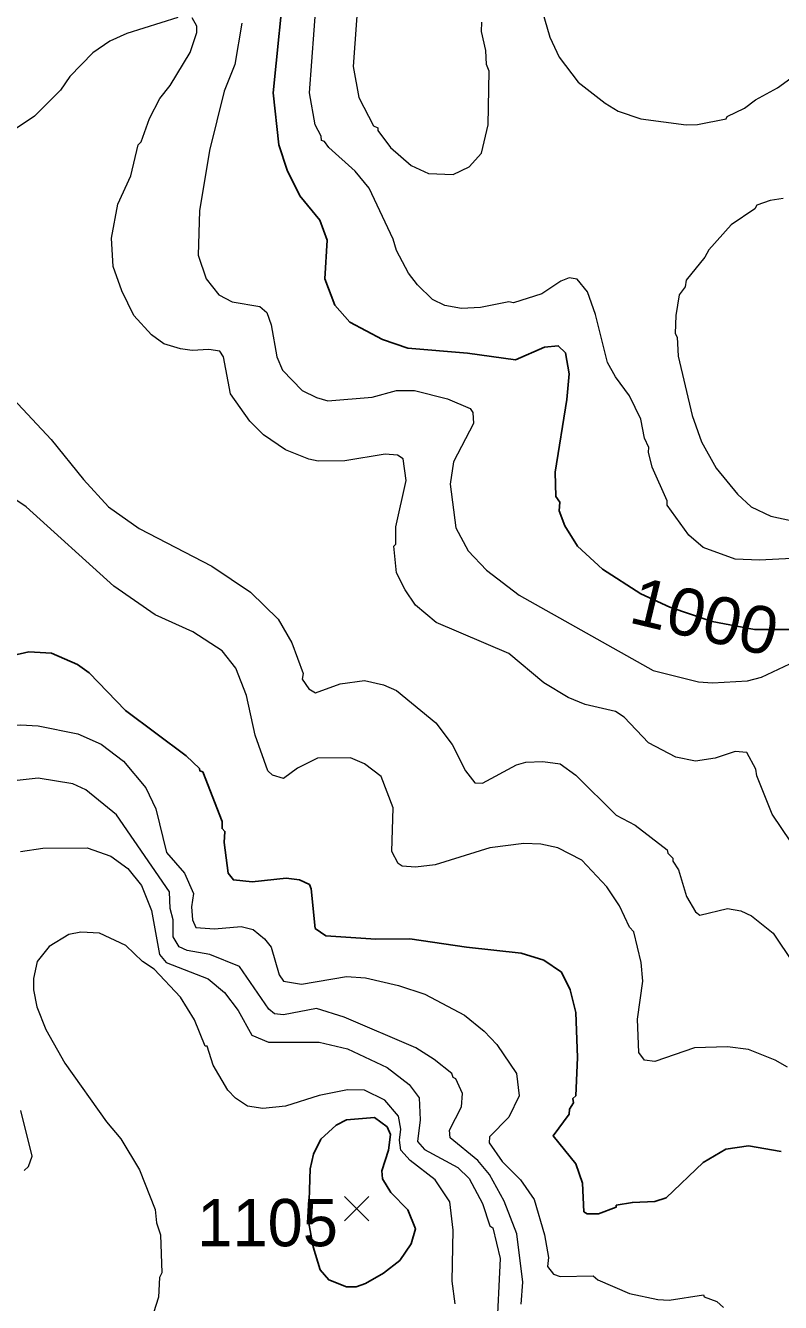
# Model space of a CAD drawing. Extents: x 265.7 to 292.1, y 7676.2 to 7704.2.
# Drawn here: x 289.907 to 291.184, y 7678.572 to 7680.733 of the extents above; entities that cross this region are included whole.
import ezdxf
from ezdxf.enums import TextEntityAlignment as Align

# ---------------------------------------------------------------- set-up
doc = ezdxf.new("R2010")
doc.units = 0
doc.header["$LTSCALE"] = 0.032
for name, color, linetype, lineweight in [('1', 7, 'Continuous', 25), ('2', 7, 'Continuous', 13), ('21', 7, 'Continuous', 25)]:
    doc.layers.add(name, color=color, linetype=linetype, lineweight=lineweight)
doc.layers.add('61', color=7, linetype='Continuous')

msp = doc.modelspace()

# ---------------------------------------------------------------- linework, layer by layer
at = {"layer": '1'}
for points in [[(290.3464, 7680.8268), (290.3256, 7680.6193), (290.3352, 7680.5316), (290.3495, 7680.4885), (290.3711, 7680.4454), (290.4046, 7680.4039), (290.4174, 7680.3704), (290.4134, 7680.3049), (290.4301, 7680.2602), (290.4557, 7680.2315), (290.5107, 7680.202), (290.5538, 7680.1876), (290.6544, 7680.1789), (290.7358, 7680.1677)], [(290.7358, 7680.1677), (290.7852, 7680.1892), (290.8084, 7680.1916), (290.8203, 7680.1797), (290.8267, 7680.1438), (290.8227, 7680.1007), (290.8028, 7679.9778)], [(290.8028, 7679.9778), (290.8044, 7679.9363), (290.8108, 7679.9267), (290.81, 7679.9123), (290.8195, 7679.8868), (290.8411, 7679.8525), (290.8834, 7679.8134), (290.948, 7679.7719), (290.997, 7679.7492), (291.0687, 7679.7247), (291.1403, 7679.7115), (291.2176, 7679.7115)], [(291.1858, 7678.8279), (291.13, 7678.8375), (291.0917, 7678.8319), (291.0534, 7678.8095), (290.9911, 7678.7497), (290.972, 7678.7433), (290.9337, 7678.7417), (290.9065, 7678.7369), (290.9065, 7678.7337), (290.8762, 7678.7226), (290.8571, 7678.7226), (290.8515, 7678.7258), (290.8491, 7678.7745), (290.8379, 7678.8072), (290.7996, 7678.8542), (290.8267, 7678.891), (290.8275, 7678.8997), (290.8339, 7678.9101), (290.8331, 7678.9173), (290.8379, 7678.9221), (290.8411, 7678.9867), (290.8379, 7679.0633), (290.8283, 7679.1016), (290.814, 7679.1311), (290.7836, 7679.1519), (290.7453, 7679.1638), (290.6528, 7679.1734), (290.557, 7679.1878), (290.4996, 7679.187), (290.415, 7679.1926), (290.3966, 7679.2053), (290.3902, 7679.2724), (290.387, 7679.2796), (290.3703, 7679.2875), (290.348, 7679.2907), (290.2905, 7679.2843), (290.2586, 7679.2875), (290.2498, 7679.2987), (290.2426, 7679.3506), (290.2442, 7679.3697), (290.2394, 7679.3745), (290.2394, 7679.3865), (290.2067, 7679.4703), (290.2019, 7679.4719), (290.2011, 7679.4759), (290.1788, 7679.4974), (290.0759, 7679.574), (290.0144, 7679.6378), (289.9945, 7679.6522), (289.9506, 7679.6713), (289.9123, 7679.6737), (289.8851, 7679.6674)]]:
    msp.add_lwpolyline(points, dxfattribs=at)
msp.add_lwpolyline([(290.3856, 7678.7093), (290.3933, 7678.6663), (290.4054, 7678.6276), (290.4198, 7678.6109), (290.4501, 7678.5989), (290.4661, 7678.5989), (290.482, 7678.6045), (290.5123, 7678.622), (290.5403, 7678.6436), (290.5594, 7678.6715), (290.5666, 7678.697), (290.5538, 7678.729), (290.5251, 7678.7585), (290.5107, 7678.7816), (290.5099, 7678.7952), (290.5211, 7678.8303), (290.5243, 7678.8566), (290.5187, 7678.8694), (290.4972, 7678.8854), (290.4501, 7678.8814), (290.4325, 7678.8726), (290.4062, 7678.8486), (290.3942, 7678.8231), (290.3886, 7678.7984)], close=True, dxfattribs=at)
at = {"layer": '2'}
for points in [[(290.4724, 7680.8204), (290.4613, 7680.664), (290.4708, 7680.6114), (290.4956, 7680.5635), (290.5028, 7680.5603), (290.5028, 7680.5555), (290.5243, 7680.5268), (290.5594, 7680.4964), (290.5889, 7680.4829), (290.6304, 7680.4813), (290.6576, 7680.4941), (290.6783, 7680.5172), (290.6895, 7680.5651), (290.6911, 7680.656), (290.6871, 7680.6672), (290.6855, 7680.6912), (290.6783, 7680.7231), (290.6791, 7680.739)], [(291.2257, 7679.8325), (291.1491, 7679.8286), (291.1076, 7679.8301), (291.0534, 7679.8501), (291.0294, 7679.8708), (290.9927, 7679.9219), (290.9927, 7679.9291), (290.9672, 7679.9858), (290.9608, 7680.0113), (290.9616, 7680.0193), (290.9544, 7680.0352), (290.948, 7680.0671), (290.9289, 7680.107), (290.9049, 7680.139), (290.8914, 7680.1629), (290.8714, 7680.2443), (290.8579, 7680.2826), (290.8403, 7680.3041), (290.8267, 7680.3065), (290.8124, 7680.3009), (290.7805, 7680.2794), (290.7326, 7680.2642), (290.7246, 7680.2658), (290.6767, 7680.2563), (290.6448, 7680.2547), (290.6161, 7680.2595), (290.5953, 7680.2698), (290.5698, 7680.2946), (290.5546, 7680.3145), (290.5347, 7680.3528), (290.5291, 7680.372), (290.4884, 7680.4581), (290.4645, 7680.4869), (290.4198, 7680.5268), (290.4126, 7680.5371), (290.4078, 7680.5387), (290.407, 7680.5459), (290.3966, 7680.5651), (290.3871, 7680.6193), (290.399, 7680.7789)], [(290.7812, 7680.7582), (290.794, 7680.7135), (290.81, 7680.68), (290.8419, 7680.6377), (290.8874, 7680.6018), (290.9097, 7680.5882), (290.948, 7680.5754), (291.0246, 7680.5651), (291.0438, 7680.5659), (291.0925, 7680.5754), (291.0941, 7680.5794), (291.1236, 7680.5938), (291.1419, 7680.6074), (291.1794, 7680.6281), (291.2145, 7680.6536)], [(290.1644, 7680.747), (290.0782, 7680.7199), (290.0495, 7680.7071), (290.0208, 7680.6872), (289.9817, 7680.6473), (289.9657, 7680.6241), (289.9218, 7680.5802), (289.8596, 7680.5387), (289.8165, 7680.518), (289.7607, 7680.5092), (289.6825, 7680.526), (289.5947, 7680.526), (289.5899, 7680.5228), (289.4989, 7680.5172), (289.4606, 7680.522), (289.4231, 7680.5435), (289.3968, 7680.5691), (289.3776, 7680.6018), (289.3505, 7680.68), (289.3441, 7680.7191), (289.3393, 7680.7207), (289.3369, 7680.7263), (289.3266, 7680.7334)], [(290.9201, 7679.5628), (290.9049, 7679.5724), (290.8539, 7679.5844), (290.8251, 7679.5963), (290.7836, 7679.6211), (290.7246, 7679.6706), (290.6017, 7679.7232), (290.5666, 7679.7527), (290.549, 7679.7783), (290.5347, 7679.807), (290.5299, 7679.8525), (290.5331, 7679.8557), (290.5331, 7679.8852), (290.5506, 7679.9634), (290.5459, 7680.0001), (290.5363, 7680.0065), (290.5155, 7680.0081), (290.4469, 7679.9969), (290.4022, 7679.9961), (290.3862, 7679.9993), (290.3464, 7680.0153), (290.3096, 7680.0408), (290.2865, 7680.064), (290.2538, 7680.1102), (290.2418, 7680.1725), (290.2354, 7680.1821), (290.2171, 7680.1852), (290.1884, 7680.1836), (290.1692, 7680.186), (290.1405, 7680.1948), (290.1197, 7680.21), (290.0902, 7680.2427), (290.0695, 7680.2842), (290.0551, 7680.3257), (290.0519, 7680.3736), (290.0631, 7680.431), (290.0846, 7680.4789), (290.0974, 7680.5316), (290.1022, 7680.5363), (290.1165, 7680.5762), (290.1341, 7680.6098), (290.1517, 7680.6321), (290.1852, 7680.688), (290.1963, 7680.7215), (290.1963, 7680.7326), (290.1884, 7680.7462)], [(290.2729, 7680.7374), (290.261, 7680.6672), (290.2426, 7680.6225), (290.2179, 7680.522), (290.2011, 7680.4198), (290.1987, 7680.3448), (290.2123, 7680.3049), (290.2338, 7680.2778), (290.2562, 7680.2658), (290.3033, 7680.2579), (290.3152, 7680.2475), (290.3224, 7680.2267), (290.332, 7680.1725), (290.3416, 7680.1501), (290.3751, 7680.1158), (290.399, 7680.1039), (290.4182, 7680.0983), (290.4932, 7680.1046), (290.5347, 7680.1158), (290.565, 7680.1158), (290.6209, 7680.1015), (290.6592, 7680.0855), (290.6639, 7680.0783), (290.6647, 7680.06), (290.6312, 7679.9953), (290.6256, 7679.957), (290.6352, 7679.8836), (290.656, 7679.8445), (290.6871, 7679.8118), (290.7422, 7679.7695), (290.9688, 7679.6418), (291.0454, 7679.6227), (291.0693, 7679.6211), (291.1284, 7679.6243), (291.1523, 7679.6307)], [(291.189, 7680.4406), (291.1667, 7680.4374), (291.1443, 7680.4294), (291.1411, 7680.423), (291.1012, 7680.3959), (291.0629, 7680.3536), (291.0565, 7680.3416), (291.0246, 7680.3025), (291.023, 7680.2914), (291.0127, 7680.2778), (291.0071, 7680.2427), (291.0063, 7680.2124), (291.0095, 7680.206), (291.0111, 7680.1741), (291.035, 7680.0735), (291.051, 7680.0288), (291.0757, 7679.9842), (291.1116, 7679.9403), (291.1348, 7679.9187), (291.1683, 7679.9028), (291.2018, 7679.8956)], [(289.8859, 7680.1015), (289.9498, 7680.0328), (290.0048, 7679.965), (290.0471, 7679.9187), (290.099, 7679.882), (290.2219, 7679.8182), (290.2873, 7679.7743), (290.3344, 7679.7288), (290.3575, 7679.6889), (290.3767, 7679.637), (290.3751, 7679.6275), (290.3863, 7679.6107), (290.3974, 7679.6043), (290.4389, 7679.6195), (290.4804, 7679.6251), (290.5123, 7679.6179), (290.5347, 7679.6083), (290.6009, 7679.5533), (290.6288, 7679.5166), (290.6512, 7679.4719), (290.6671, 7679.4519), (290.6799, 7679.4511), (290.7374, 7679.4822), (290.7533, 7679.487), (290.7821, 7679.4878), (290.8116, 7679.4838), (290.8379, 7679.4647), (290.9065, 7679.3969), (290.9385, 7679.3801), (290.9927, 7679.3386), (290.9935, 7679.333), (291.0023, 7679.3242), (291.0023, 7679.3195), (291.0119, 7679.3043), (291.0254, 7679.2596), (291.0406, 7679.2333), (291.0478, 7679.2277), (291.0949, 7679.2389), (291.1172, 7679.2349), (291.1355, 7679.2269), (291.1723, 7679.1974), (291.2066, 7679.1463)], [(291.1962, 7678.9707), (291.1754, 7678.9827), (291.13, 7679.0003), (291.0949, 7679.0051), (291.039, 7679.0035), (290.972, 7678.9803), (290.9544, 7678.9827), (290.9448, 7678.9955), (290.9424, 7679.0521), (290.9512, 7679.116), (290.9488, 7679.1479), (290.9361, 7679.1998), (290.9289, 7679.2077), (290.9121, 7679.2437), (290.8906, 7679.2756), (290.8483, 7679.321), (290.8076, 7679.3418), (290.7789, 7679.3482), (290.7501, 7679.349), (290.6927, 7679.3418), (290.6001, 7679.3131), (290.5666, 7679.3091), (290.5443, 7679.3107), (290.5371, 7679.3155), (290.5267, 7679.3354), (290.5291, 7679.4096), (290.5083, 7679.4623), (290.4804, 7679.4838), (290.4565, 7679.4942), (290.4006, 7679.4934), (290.3671, 7679.4766), (290.3432, 7679.4591), (290.3248, 7679.4647), (290.3168, 7679.4719), (290.2953, 7679.5325), (290.2809, 7679.5995), (290.2626, 7679.6458), (290.2394, 7679.6753), (290.19, 7679.7073), (290.1261, 7679.736), (290.0559, 7679.7847), (289.9075, 7679.9187), (289.8157, 7679.9802)], [(291.1523, 7679.6307), (291.2002, 7679.653), (291.256, 7679.6737), (291.3279, 7679.6841), (291.3446, 7679.6833), (291.3558, 7679.665), (291.3518, 7679.6554)], [(289.5931, 7679.4256), (289.6362, 7679.4591), (289.716, 7679.5134), (289.8053, 7679.5437), (289.8979, 7679.5501), (289.9282, 7679.5485), (289.9953, 7679.5349)], [(291.1276, 7679.503), (291.1076, 7679.5046), (291.0741, 7679.4934), (291.0406, 7679.4886), (291.0071, 7679.495), (290.9608, 7679.5197), (290.9201, 7679.5628)], [(289.9953, 7679.5349), (290.0344, 7679.5173), (290.0727, 7679.4886), (290.1102, 7679.4431), (290.1269, 7679.408), (290.1453, 7679.3338), (290.1756, 7679.2987), (290.1908, 7679.2644), (290.1876, 7679.2421), (290.1892, 7679.2197), (290.1947, 7679.2069), (290.2267, 7679.2045), (290.2714, 7679.2085), (290.2921, 7679.2037), (290.3113, 7679.1878), (290.3224, 7679.1734), (290.336, 7679.1271), (290.3432, 7679.116), (290.3735, 7679.1112), (290.4501, 7679.1239), (290.482, 7679.1216), (290.5379, 7679.1088), (290.5826, 7679.0944), (290.6496, 7679.0585), (290.6831, 7679.0314), (290.7046, 7679.0091), (290.7374, 7678.9596), (290.7421, 7678.9221), (290.7246, 7678.8862), (290.6919, 7678.8526), (290.6911, 7678.8423), (290.7134, 7678.8112), (290.7445, 7678.78), (290.7677, 7678.7465), (290.7852, 7678.6867), (290.7916, 7678.6484), (290.79, 7678.6332), (290.8004, 7678.6204), (290.8116, 7678.6164), (290.8674, 7678.6172), (290.8754, 7678.6109), (290.9289, 7678.5877), (290.9768, 7678.5773), (290.9959, 7678.5765), (291.0542, 7678.5853), (291.055, 7678.5821), (291.0765, 7678.5742), (291.0877, 7678.5638)], [(291.2018, 7679.3522), (291.1706, 7679.3985), (291.1443, 7679.4639), (291.1427, 7679.4751), (291.1276, 7679.503)], [(290.6448, 7678.9037), (290.6464, 7678.9261), (290.6352, 7678.9508), (290.6304, 7678.9532), (290.628, 7678.9596), (290.5985, 7678.9835), (290.5674, 7679.0035), (290.4461, 7679.0553), (290.399, 7679.0697), (290.3432, 7679.0593), (290.328, 7679.0609), (290.3184, 7679.0689), (290.269, 7679.1407), (290.2187, 7679.1615), (290.1804, 7679.1678), (290.1668, 7679.1742), (290.1564, 7679.191), (290.1564, 7679.2197), (290.1517, 7679.2389), (290.1501, 7679.2676), (290.0607, 7679.3977), (290.0088, 7679.4399), (289.9865, 7679.4503), (289.9282, 7679.4599), (289.8724, 7679.4535)], [(289.8979, 7679.3354), (289.9362, 7679.341), (290.0112, 7679.3418), (290.0511, 7679.3274), (290.0798, 7679.3067), (290.103, 7679.278), (290.1197, 7679.2357), (290.1333, 7679.1615), (290.1445, 7679.1479), (290.2155, 7679.12), (290.2434, 7679.0968), (290.2666, 7679.0665), (290.2897, 7679.025), (290.3176, 7679.013), (290.4038, 7679.013), (290.4517, 7679.0019), (290.5187, 7678.9699), (290.5562, 7678.9412), (290.573, 7678.9189), (290.5746, 7678.8814), (290.5698, 7678.8447), (290.5818, 7678.8311), (290.6384, 7678.8008), (290.6576, 7678.7824), (290.6799, 7678.7401), (290.6927, 7678.7018), (290.6975, 7678.6986), (290.7102, 7678.6468), (290.7038, 7678.5183)], [(290.6336, 7678.5702), (290.6288, 7678.6085), (290.6304, 7678.6947), (290.6248, 7678.7425), (290.6001, 7678.78), (290.5578, 7678.8127), (290.5419, 7678.8303), (290.5395, 7678.8471), (290.5419, 7678.8654), (290.5379, 7678.8878), (290.5147, 7678.9149), (290.4804, 7678.9316), (290.4517, 7678.9324), (290.4038, 7678.9229), (290.3464, 7678.9045), (290.3081, 7678.9005), (290.2825, 7678.9045), (290.2618, 7678.9181), (290.249, 7678.9316), (290.2243, 7678.9739), (290.2139, 7679.0059), (290.2107, 7679.0059), (290.1924, 7679.0505), (290.1692, 7679.0888), (290.1245, 7679.1367), (290.1046, 7679.1495), (290.0766, 7679.1766), (290.032, 7679.1974), (290, 7679.199), (289.9801, 7679.195), (289.9466, 7679.175), (289.9266, 7679.1495), (289.9202, 7679.1208), (289.9202, 7679.1016), (289.9258, 7679.0729), (289.941, 7679.0346), (289.9729, 7678.9771), (290.0439, 7678.8782), (290.0679, 7678.8495), (290.0998, 7678.7968)], [(290.7382, 7678.6883), (290.7166, 7678.7441), (290.6919, 7678.7888), (290.6719, 7678.8128), (290.6256, 7678.851), (290.624, 7678.8638), (290.6448, 7678.9037)], [(289.9043, 7678.796), (289.9115, 7678.8024), (289.9179, 7678.8199), (289.8987, 7678.8973)], [(290.0998, 7678.7968), (290.1261, 7678.7298), (290.1285, 7678.7074), (290.1349, 7678.6867), (290.1373, 7678.6228), (290.1333, 7678.6149), (290.1317, 7678.5813)], [(290.7453, 7678.5694), (290.7485, 7678.6069), (290.7382, 7678.6883)], [(290.1317, 7678.5813), (290.0798, 7678.4186)]]:
    msp.add_lwpolyline(points, dxfattribs=at)
at = {"layer": '21'}
for p, q in [((290.4464, 7678.752), (290.4876, 7678.7108)), ((290.4876, 7678.752), (290.4464, 7678.7108))]:
    msp.add_line(p, q, dxfattribs=at)

# ---------------------------------------------------------------- texts
at = {"layer": '61', "width": 1.05}
msp.add_text('1000', height=0.08, rotation=346.476, dxfattribs=at).set_placement((291.0468, 7679.6945), align=Align.CENTER)
at = {"layer": '61'}
msp.add_text('1105', height=0.08, dxfattribs=at).set_placement((290.3164, 7678.6675), align=Align.CENTER)

doc.saveas('drawing.dxf')
